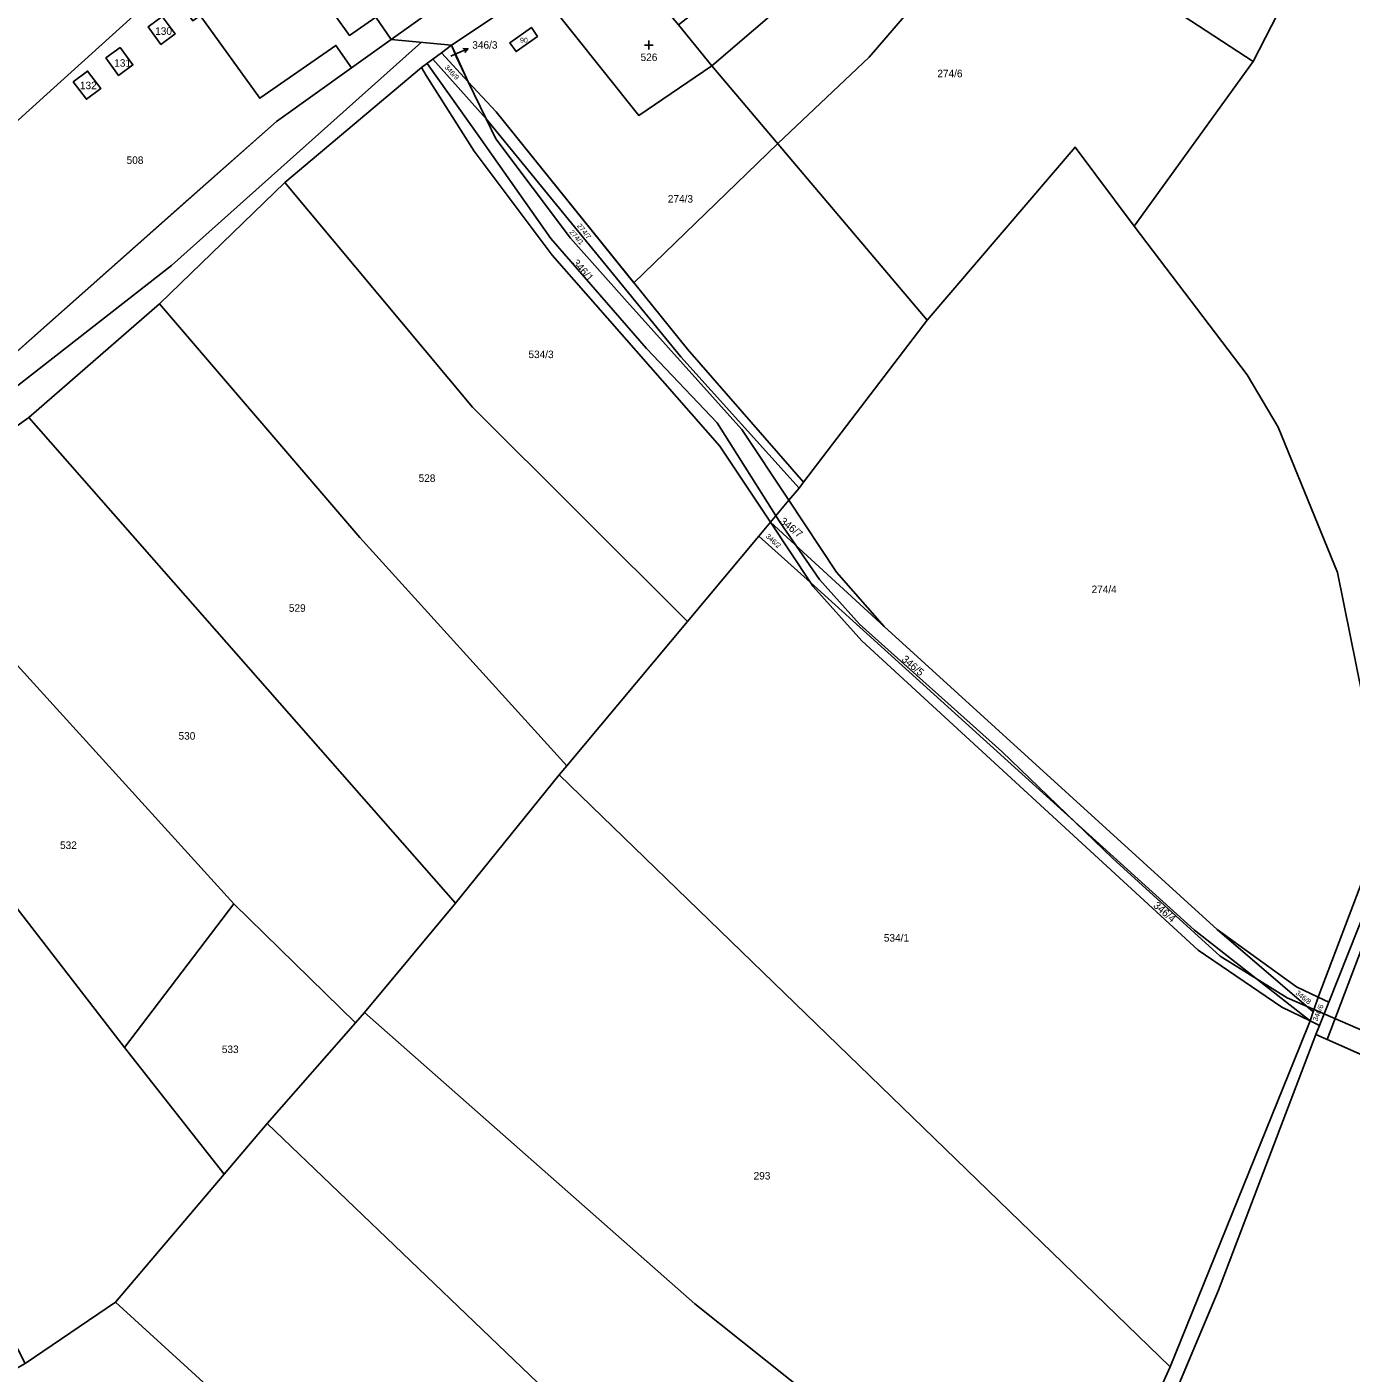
# Model space of a CAD drawing. Extents: x -590606 to -587796, y -1065936 to -1062515.
# Drawn here: x -589528.2 to -589228.8, y -1065384.3 to -1065080 of the extents above; entities that cross this region are included whole.
import ezdxf

# ---------------------------------------------------------------- set-up
doc = ezdxf.new("R2010")
doc.units = 0
for name, color, linetype in [('Cesty', 7, 'Continuous'), ('Místní komunikace', 7, 'Continuous'), ('Parcela nároku', 7, 'Continuous'), ('Parcelní číslo', 7, 'Continuous'), ('Vnější obvod_ Studené', 7, 'Continuous'), ('Vnější obvod_Sobkovice', 7, 'Continuous'), ('Vrstva 30', 7, 'Continuous')]:
    doc.layers.add(name, color=color, linetype=linetype)

msp = doc.modelspace()

# ---------------------------------------------------------------- linework, layer by layer
at = {"layer": 'Cesty'}
msp.add_lwpolyline([(-589437.69, -1065088.26), (-589426.06, -1065104.75), (-589409.75, -1065127.88), (-589388.17, -1065152.71), (-589372.16, -1065169.52), (-589358.09, -1065191.81), (-589349, -1065204.91), (-589339.96, -1065215.02), (-589307.79, -1065243.81), (-589282.78, -1065267.95), (-589258.43, -1065290.1), (-589243.3, -1065299.54), (-589211.38, -1065313.41)], dxfattribs=at)
at = {"layer": 'Místní komunikace'}
msp.add_lwpolyline([(-590032.24, -1065438.38), (-590006.45, -1065407.31), (-589942.84, -1065337.53), (-589895.42, -1065285.51), (-589869.8, -1065266.79), (-589828.89, -1065251.03), (-589784.72, -1065247.93), (-589748.82, -1065251.39), (-589723.97, -1065262.33), (-589705.87, -1065274.36), (-589691.01, -1065280.58), (-589668.31, -1065279.77), (-589639.11, -1065264.21), (-589592.5, -1065212.05), (-589561.97, -1065185.83), (-589495.54, -1065133.99), (-589439.02, -1065083.5)], dxfattribs=at)
at = {"layer": 'Parcela nároku'}
for points in [[(-589164.98, -1064928.86), (-589178.94, -1064950.61), (-589205.41, -1065000.22), (-589232.77, -1065042.25), (-589228.87, -1065044.77), (-589250.95, -1065087.85), (-589277.85, -1065125.06), (-589252.37, -1065158.64), (-589245.33, -1065170.48), (-589231.95, -1065203.34), (-589224.84, -1065238.37), (-589201.19, -1065210.22), (-589196.32, -1065193.25), (-589184.2, -1065137.36), (-589161.34, -1065072.9), (-589151.23, -1065033.97), (-589150.92, -1065007.3), (-589154.33, -1064973.17)], [(-589232.77, -1065042.25), (-589228.87, -1065044.77), (-589250.95, -1065087.85), (-589286.33, -1065064.68), (-589316.82, -1065040.39), (-589324.9, -1065034.23), (-589308.34, -1064997.6), (-589300.48, -1065000.08), (-589294.61, -1064990.73), (-589279.85, -1065008.58)], [(-589478.37, -1065016.09), (-589503.15, -1065036.55), (-589538.37, -1065066.07), (-589542.82, -1065094.63), (-589547.12, -1065116.37), (-589543.73, -1065113.31), (-589522.14, -1065093.79), (-589504.94, -1065078.24), (-589494.98, -1065069.24), (-589468.15, -1065044.98), (-589458.09, -1065038.68), (-589454.84, -1065036.64), (-589476.59, -1065010.77), (-589478.86, -1065012.72)], [(-589360.23, -1065050.24), (-589349.8, -1065045.2), (-589353.53, -1065041.99), (-589337.1, -1065025.05), (-589324.9, -1065034.23), (-589316.82, -1065040.39), (-589373.33, -1065088.79), (-589380.88, -1065079.54), (-589354.19, -1065058.62)], [(-589454.84, -1065036.64), (-589446.88, -1065047.17), (-589451.25, -1065051.25), (-589451.84, -1065050.59), (-589463.64, -1065060.28), (-589458.93, -1065065.12), (-589456.3, -1065069), (-589461.79, -1065072.85), (-589455.31, -1065081.93), (-589449.3, -1065077.79), (-589445.82, -1065082.83), (-589454.83, -1065089.29), (-589458.35, -1065084.21), (-589475.58, -1065096.14), (-589489.05, -1065077.46), (-589487.45, -1065076.26), (-589490.33, -1065072.29), (-589491.94, -1065073.46), (-589494.98, -1065069.24), (-589468.15, -1065044.98), (-589458.09, -1065038.68)], [(-589286.33, -1065064.68), (-589316.82, -1065040.39), (-589373.33, -1065088.79), (-589324.71, -1065146.34), (-589291.24, -1065107.19), (-589277.85, -1065125.06), (-589250.95, -1065087.85)], [(-589438.79, -1065057.06), (-589428.09, -1065070.14), (-589445.82, -1065082.83), (-589449.3, -1065077.79), (-589455.31, -1065081.93), (-589461.79, -1065072.85), (-589456.3, -1065069), (-589458.93, -1065065.12), (-589463.64, -1065060.28), (-589451.84, -1065050.59), (-589451.25, -1065051.25), (-589446.88, -1065047.17)], [(-589380.88, -1065079.54), (-589373.33, -1065088.79), (-589389.87, -1065100.03), (-589412.82, -1065071.17), (-589396, -1065061.67)], [(-589504.94, -1065078.24), (-589494.98, -1065069.24), (-589491.94, -1065073.46), (-589493.57, -1065074.64), (-589490.67, -1065078.66), (-589489.05, -1065077.46), (-589475.58, -1065096.14), (-589458.35, -1065084.21), (-589454.83, -1065089.29), (-589471.77, -1065101.42), (-589491.61, -1065118.9), (-589527.75, -1065151), (-589531.71, -1065154.52), (-589546.14, -1065118.8), (-589547.12, -1065116.37), (-589543.73, -1065113.31), (-589522.14, -1065093.79)], [(-589389.87, -1065100.03), (-589412.82, -1065071.17), (-589432.22, -1065084.17), (-589431.18, -1065086.73), (-589428.43, -1065092.41), (-589422.14, -1065099.19), (-589378.86, -1065152.89), (-589352.63, -1065182.93), (-589324.71, -1065146.34), (-589373.33, -1065088.79)], [(-589497.6, -1065077.66), (-589500.8, -1065080.02), (-589497.91, -1065083.98), (-589494.71, -1065081.59)], [(-589497.91, -1065083.98), (-589494.71, -1065081.59), (-589497.6, -1065077.66), (-589500.8, -1065080.02)], [(-589414.14, -1065080.12), (-589412.78, -1065082.15), (-589417.62, -1065085.61), (-589419.06, -1065083.63)], [(-589412.78, -1065082.15), (-589417.62, -1065085.61), (-589419.06, -1065083.63), (-589414.14, -1065080.12)], [(-589504.25, -1065088.62), (-589507.14, -1065084.68), (-589510.36, -1065087.04), (-589507.46, -1065091.03)], [(-589510.36, -1065087.04), (-589507.46, -1065091.03), (-589504.25, -1065088.62), (-589507.14, -1065084.68)], [(-589432.22, -1065084.17), (-589431.18, -1065086.73), (-589428.43, -1065092.41), (-589434.49, -1065085.87)], [(-589393.14, -1065141.51), (-589366.55, -1065171.03), (-589355.95, -1065187.03), (-589360.13, -1065192.01), (-589371.58, -1065174.83), (-589396.95, -1065145.85), (-589409.44, -1065131.62), (-589427.11, -1065108.07), (-589437.98, -1065091.02), (-589438.97, -1065089.22), (-589436.41, -1065087.3), (-589424.35, -1065100.82), (-589422.16, -1065105.35), (-589405.28, -1065127.79)], [(-589434.49, -1065085.87), (-589428.43, -1065092.41), (-589424.35, -1065100.82), (-589436.41, -1065087.3)], [(-589511.52, -1065093.97), (-589514.5, -1065090.01), (-589517.73, -1065092.44), (-589514.74, -1065096.38)], [(-589517.73, -1065092.44), (-589514.74, -1065096.38), (-589511.52, -1065093.97), (-589514.5, -1065090.01)], [(-589360.13, -1065192.01), (-589371.58, -1065174.83), (-589396.95, -1065145.85), (-589409.44, -1065131.62), (-589427.11, -1065108.07), (-589437.98, -1065091.02), (-589438.97, -1065089.22), (-589469.86, -1065115.16), (-589427.46, -1065165.99), (-589378.84, -1065214.4), (-589362.73, -1065195.18)], [(-589422.14, -1065099.19), (-589378.86, -1065152.89), (-589352.63, -1065182.93), (-589353.65, -1065184.3), (-589380.37, -1065154.61), (-589424.35, -1065100.82), (-589428.43, -1065092.41)], [(-589424.35, -1065100.82), (-589380.37, -1065154.61), (-589353.65, -1065184.3), (-589355.95, -1065187.03), (-589366.55, -1065171.03), (-589393.14, -1065141.51), (-589405.28, -1065127.79), (-589422.16, -1065105.35)], [(-589231.95, -1065203.34), (-589245.33, -1065170.48), (-589252.37, -1065158.64), (-589277.85, -1065125.06), (-589291.24, -1065107.19), (-589324.71, -1065146.34), (-589352.63, -1065182.93), (-589353.65, -1065184.3), (-589355.95, -1065187.03), (-589345.18, -1065203.28), (-589334.43, -1065215.53), (-589259.13, -1065284.03), (-589241.17, -1065297.05), (-589236.27, -1065299.4), (-589225.36, -1065270.61), (-589215.81, -1065250.37), (-589224.84, -1065238.37)], [(-589427.46, -1065165.99), (-589378.84, -1065214.4), (-589406.14, -1065247.05), (-589452.92, -1065195.46), (-589498.25, -1065142.61), (-589469.86, -1065115.16)], [(-589452.92, -1065195.46), (-589406.14, -1065247.05), (-589407.84, -1065249.12), (-589431.32, -1065278.11), (-589527.79, -1065168.29), (-589498.25, -1065142.61)], [(-589527.79, -1065168.29), (-589431.32, -1065278.11), (-589451.89, -1065302.84), (-589453.94, -1065305.16), (-589481.4, -1065278.29), (-589530.42, -1065224.3), (-589557.97, -1065189.9)], [(-589355.95, -1065187.03), (-589345.18, -1065203.28), (-589334.43, -1065215.53), (-589360.13, -1065192.01)], [(-589362.73, -1065195.18), (-589360.13, -1065192.01), (-589351.04, -1065205.65)], [(-589259.13, -1065284.03), (-589237.39, -1065302.65), (-589238.1, -1065304.73), (-589264.28, -1065284.23), (-589351.04, -1065205.65), (-589360.13, -1065192.01), (-589334.43, -1065215.53)], [(-589215.81, -1065250.37), (-589225.36, -1065270.61), (-589236.27, -1065299.4), (-589233.91, -1065300.53), (-589191.9, -1065194.84), (-589196.32, -1065193.25), (-589201.19, -1065210.22), (-589205.63, -1065225.67)], [(-589406.14, -1065247.05), (-589378.84, -1065214.4), (-589362.73, -1065195.18), (-589351.04, -1065205.65), (-589350.51, -1065206.44), (-589339.45, -1065218.8), (-589263.42, -1065288.76), (-589244.52, -1065301.59), (-589238.1, -1065304.73), (-589240.47, -1065310.53), (-589269.78, -1065382.93), (-589407.84, -1065249.12)], [(-589235.99, -1065305.76), (-589233.91, -1065300.53), (-589191.9, -1065194.84), (-589186.96, -1065196.74), (-589202.89, -1065230.22), (-589211.33, -1065248.53), (-589221.68, -1065275.8), (-589234.25, -1065308.93), (-589236.8, -1065307.79)], [(-589351.04, -1065205.65), (-589264.28, -1065284.23), (-589238.1, -1065304.73), (-589244.52, -1065301.59), (-589263.42, -1065288.76), (-589339.45, -1065218.8), (-589350.51, -1065206.44)], [(-589506.17, -1065310.71), (-589554.02, -1065248.84), (-589580.96, -1065211.55), (-589581.03, -1065211.81), (-589595.04, -1065252.55), (-589528.61, -1065382.21), (-589508.15, -1065368.32), (-589483.62, -1065339.41)], [(-589554.02, -1065248.84), (-589530.42, -1065224.3), (-589481.4, -1065278.29), (-589506.17, -1065310.71)], [(-589451.89, -1065302.84), (-589431.32, -1065278.11), (-589407.84, -1065249.12), (-589269.78, -1065382.93), (-589291.11, -1065430.27), (-589301.77, -1065428.8), (-589377.22, -1065368.71)], [(-589089.12, -1065349.27), (-589055.42, -1065364.45), (-589055.93, -1065366.79), (-589054.94, -1065380.53), (-589051.63, -1065403.17), (-589051.61, -1065404.76), (-589137.45, -1065359.1), (-589186.88, -1065333.07), (-589213.89, -1065318.01), (-589234.25, -1065308.93), (-589221.68, -1065275.8), (-589181.51, -1065295.9)], [(-589481.4, -1065278.29), (-589453.94, -1065305.16), (-589473.86, -1065327.96), (-589483.62, -1065339.41), (-589506.17, -1065310.71)], [(-589259.13, -1065284.03), (-589241.17, -1065297.05), (-589236.27, -1065299.4), (-589237.39, -1065302.65)], [(-589237.39, -1065302.65), (-589236.27, -1065299.4), (-589233.91, -1065300.53), (-589235.99, -1065305.76), (-589238.1, -1065304.73)], [(-589473.86, -1065327.96), (-589453.94, -1065305.16), (-589451.89, -1065302.84), (-589377.22, -1065368.71), (-589301.77, -1065428.8), (-589304.5, -1065433.4), (-589317.97, -1065474.02), (-589392.91, -1065405.56)], [(-589291.11, -1065430.27), (-589269.78, -1065382.93), (-589240.47, -1065310.53), (-589238.1, -1065304.73), (-589235.99, -1065305.76), (-589236.8, -1065307.79), (-589258.79, -1065365.57), (-589277.68, -1065410.37), (-589299.84, -1065456.82), (-589320.4, -1065490.99), (-589336.06, -1065519.84), (-589337.61, -1065522.54), (-589339.73, -1065520.78), (-589314.44, -1065476.94)], [(-589317.97, -1065474.02), (-589392.91, -1065405.56), (-589473.86, -1065327.96), (-589483.62, -1065339.41), (-589508.15, -1065368.32), (-589485.78, -1065388.71), (-589473.5, -1065399.81), (-589457.16, -1065413.7), (-589440.29, -1065428.35), (-589420.71, -1065444.66), (-589339.73, -1065520.78), (-589314.44, -1065476.94)], [(-589485.78, -1065388.71), (-589508.15, -1065368.32), (-589528.61, -1065382.21), (-589573.17, -1065407.41), (-589550.14, -1065435.35), (-589506.84, -1065414.13)]]:
    msp.add_lwpolyline(points, close=True, dxfattribs=at)
for points in [[(-589705.99, -1065278.61), (-589674.02, -1065288.97), (-589669.93, -1065287.88), (-589661.1, -1065285.91), (-589632.41, -1065268.81), (-589610.86, -1065237.66), (-589597.17, -1065221.79), (-589583.19, -1065208.42), (-589579.19, -1065204.99), (-589557.97, -1065189.9), (-589527.79, -1065168.29), (-589498.25, -1065142.61), (-589469.86, -1065115.16), (-589438.97, -1065089.22), (-589436.41, -1065087.3), (-589434.49, -1065085.87), (-589432.22, -1065084.17), (-589412.82, -1065071.17)], [(-589428.09, -1065070.14), (-589445.82, -1065082.83), (-589454.83, -1065089.29), (-589471.77, -1065101.42), (-589491.61, -1065118.9), (-589527.75, -1065151), (-589531.71, -1065154.52), (-589572.74, -1065186.9), (-589577.57, -1065190.24), (-589592.7, -1065199.64), (-589611.87, -1065223.17), (-589643.66, -1065262.81), (-589650.55, -1065266.18), (-589669.77, -1065276.4), (-589692.24, -1065271.98)]]:
    msp.add_lwpolyline(points, dxfattribs=at)
at = {"layer": 'Parcelní číslo'}
for p, q in [((-589432.39, -1065086.63), (-589431.26, -1065086.14)), ((-589431.26, -1065086.14), (-589428.51, -1065084.95))]:
    msp.add_line(p, q, dxfattribs=at)
msp.add_lwpolyline([(-589429.62, -1065084.89), (-589428.51, -1065084.95), (-589429.23, -1065085.8)], dxfattribs=at)
at = {"layer": 'Vnější obvod_ Studené'}
for p, q in [((-589319.48, -1065065.54), (-589337.78, -1065086.88)), ((-589445.82, -1065082.83), (-589454.83, -1065089.29)), ((-589432.22, -1065084.17), (-589445.82, -1065082.83)), ((-589428.43, -1065092.41), (-589432.22, -1065084.17)), ((-589337.78, -1065086.88), (-589358.46, -1065106.39)), ((-589454.83, -1065089.29), (-589471.77, -1065101.42)), ((-589422.14, -1065099.19), (-589428.43, -1065092.41)), ((-589390.96, -1065137.87), (-589422.14, -1065099.19)), ((-589471.77, -1065101.42), (-589531.71, -1065154.52)), ((-589358.46, -1065106.39), (-589390.96, -1065137.87))]:
    msp.add_line(p, q, dxfattribs=at)
at = {"layer": 'Vnější obvod_Sobkovice'}
for p, q in [((-589258.79, -1065365.57), (-589236.8, -1065307.79)), ((-589236.8, -1065307.79), (-589234.25, -1065308.93)), ((-589234.25, -1065308.93), (-589213.89, -1065318.01)), ((-589277.68, -1065410.37), (-589258.79, -1065365.57))]:
    msp.add_line(p, q, dxfattribs=at)
at = {"layer": 'Vrstva 30'}
for p, q in [((-589388.61, -1065084.12), (-589386.61, -1065084.12)), ((-589387.61, -1065083.12), (-589387.61, -1065085.12))]:
    msp.add_line(p, q, dxfattribs=at)

# ---------------------------------------------------------------- texts
at = {"layer": 'Parcela nároku'}
for s, height, p in [('130', 1.7, (-589499.21, -1065081.81)), ('90', 1.14, (-589416.72, -1065083.6)), ('131', 1.7, (-589508.46, -1065089.02)), ('346/3', 0.1, (-589432.58, -1065086.63)), ('526', 1.7, (-589389.47, -1065087.73)), ('274/6', 1.7, (-589322.38, -1065091.4)), ('132', 1.7, (-589516.21, -1065094.1)), ('508', 1.7, (-589505.66, -1065110.99)), ('274/3', 1.7, (-589383.31, -1065119.73)), ('534/3', 1.7, (-589414.82, -1065154.89)), ('528', 1.7, (-589439.65, -1065182.88)), ('274/4', 1.7, (-589287.51, -1065208.01)), ('529', 1.7, (-589468.98, -1065212.24)), ('530', 1.7, (-589493.92, -1065241.14)), ('532', 1.7, (-589520.71, -1065265.86)), ('534/1', 1.7, (-589334.48, -1065286.8)), ('533', 1.7, (-589484.14, -1065312)), ('293', 1.7, (-589363.92, -1065340.59))]:
    msp.add_text(s, height=height, dxfattribs=at).set_placement(p)
for s, height, rotation, p in [('346/9', 1.14, 312.4723, (-589433.87, -1065089.22)), ('274/1', 1.14, 311.3534, (-589405.67, -1065126.46)), ('274/7', 1.14, 307.9593, (-589403.9, -1065125)), ('346/1', 1.7, 311.648, (-589404.99, -1065133.47)), ('346/7', 1.7, 321.0403, (-589358.12, -1065192.06)), ('346/2', 1.14, 317.3389, (-589361.28, -1065195.31)), ('346/5', 1.7, 319.2569, (-589330.6, -1065223.2)), ('346/4', 1.7, 319.2745, (-589273.71, -1065278.87)), ('346/8', 1.14, 320.9233, (-589241.51, -1065298.6)), ('346/6', 1.14, 67.5742, (-589236.52, -1065304.92))]:
    msp.add_text(s, height=height, rotation=rotation, dxfattribs=at).set_placement(p)
at = {"layer": 'Parcelní číslo'}
msp.add_text('346/3', height=1.7, dxfattribs=at).set_placement((-589427.51, -1065084.95))

doc.saveas('drawing.dxf')
